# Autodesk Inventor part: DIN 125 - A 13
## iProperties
IsCustomPart: 1
Created: 2006-02
Part Number: DIN 125 - A 13
Material: Steel, Mild
Description: Washer
Document SubType Name: Modeling
Standard: DIN 125
Designer: Andy Moles
Standards Organization: DIN
Language: en-US
Size Designation: A 13
Categories: <MemberInstance><Categories><Category DisplayName="Fasteners" InternalName="e4da775c-781d-43d5-af7c-5136215cf5a6" Mnemonic="FSTN"><Category DisplayName="Washers
Density: 1 g/cm^3
Author: Andy Moles
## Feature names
1. Body [Extrusion]
